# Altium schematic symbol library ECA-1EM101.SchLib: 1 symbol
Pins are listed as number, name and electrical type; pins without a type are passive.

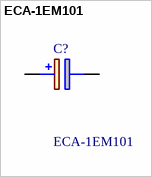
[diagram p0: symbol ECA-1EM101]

## ECA-1EM101
designator C?
PANASONIC - ECA-1EM101 - ALUMINUM ELECTROLYTIC CAPACITOR, 100UF,; Geometry.Height: 12.2mm
footprint CAPPRD250W55D630H1220
pins: 1 +, 2 -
